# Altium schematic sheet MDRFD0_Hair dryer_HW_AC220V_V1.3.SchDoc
size A3; PageSetup: Record=PageOptions¦CenterHorizontal=True¦CenterVertical=True¦PrintScale=0.73¦XCorrection=1.00¦YCorrection=1.00¦PrintKind=0¦BorderSize=5000000¦LeftOffset=0¦BottomOffset=0¦Orientation=2¦PaperLength=1000¦PaperWidth=1000¦Scale=100¦PaperSource=7¦PrintQuality=-3¦MediaType=1¦DitherType=10¦PrintScaleMode=1¦PaperKind=A4¦PaperIndex=9
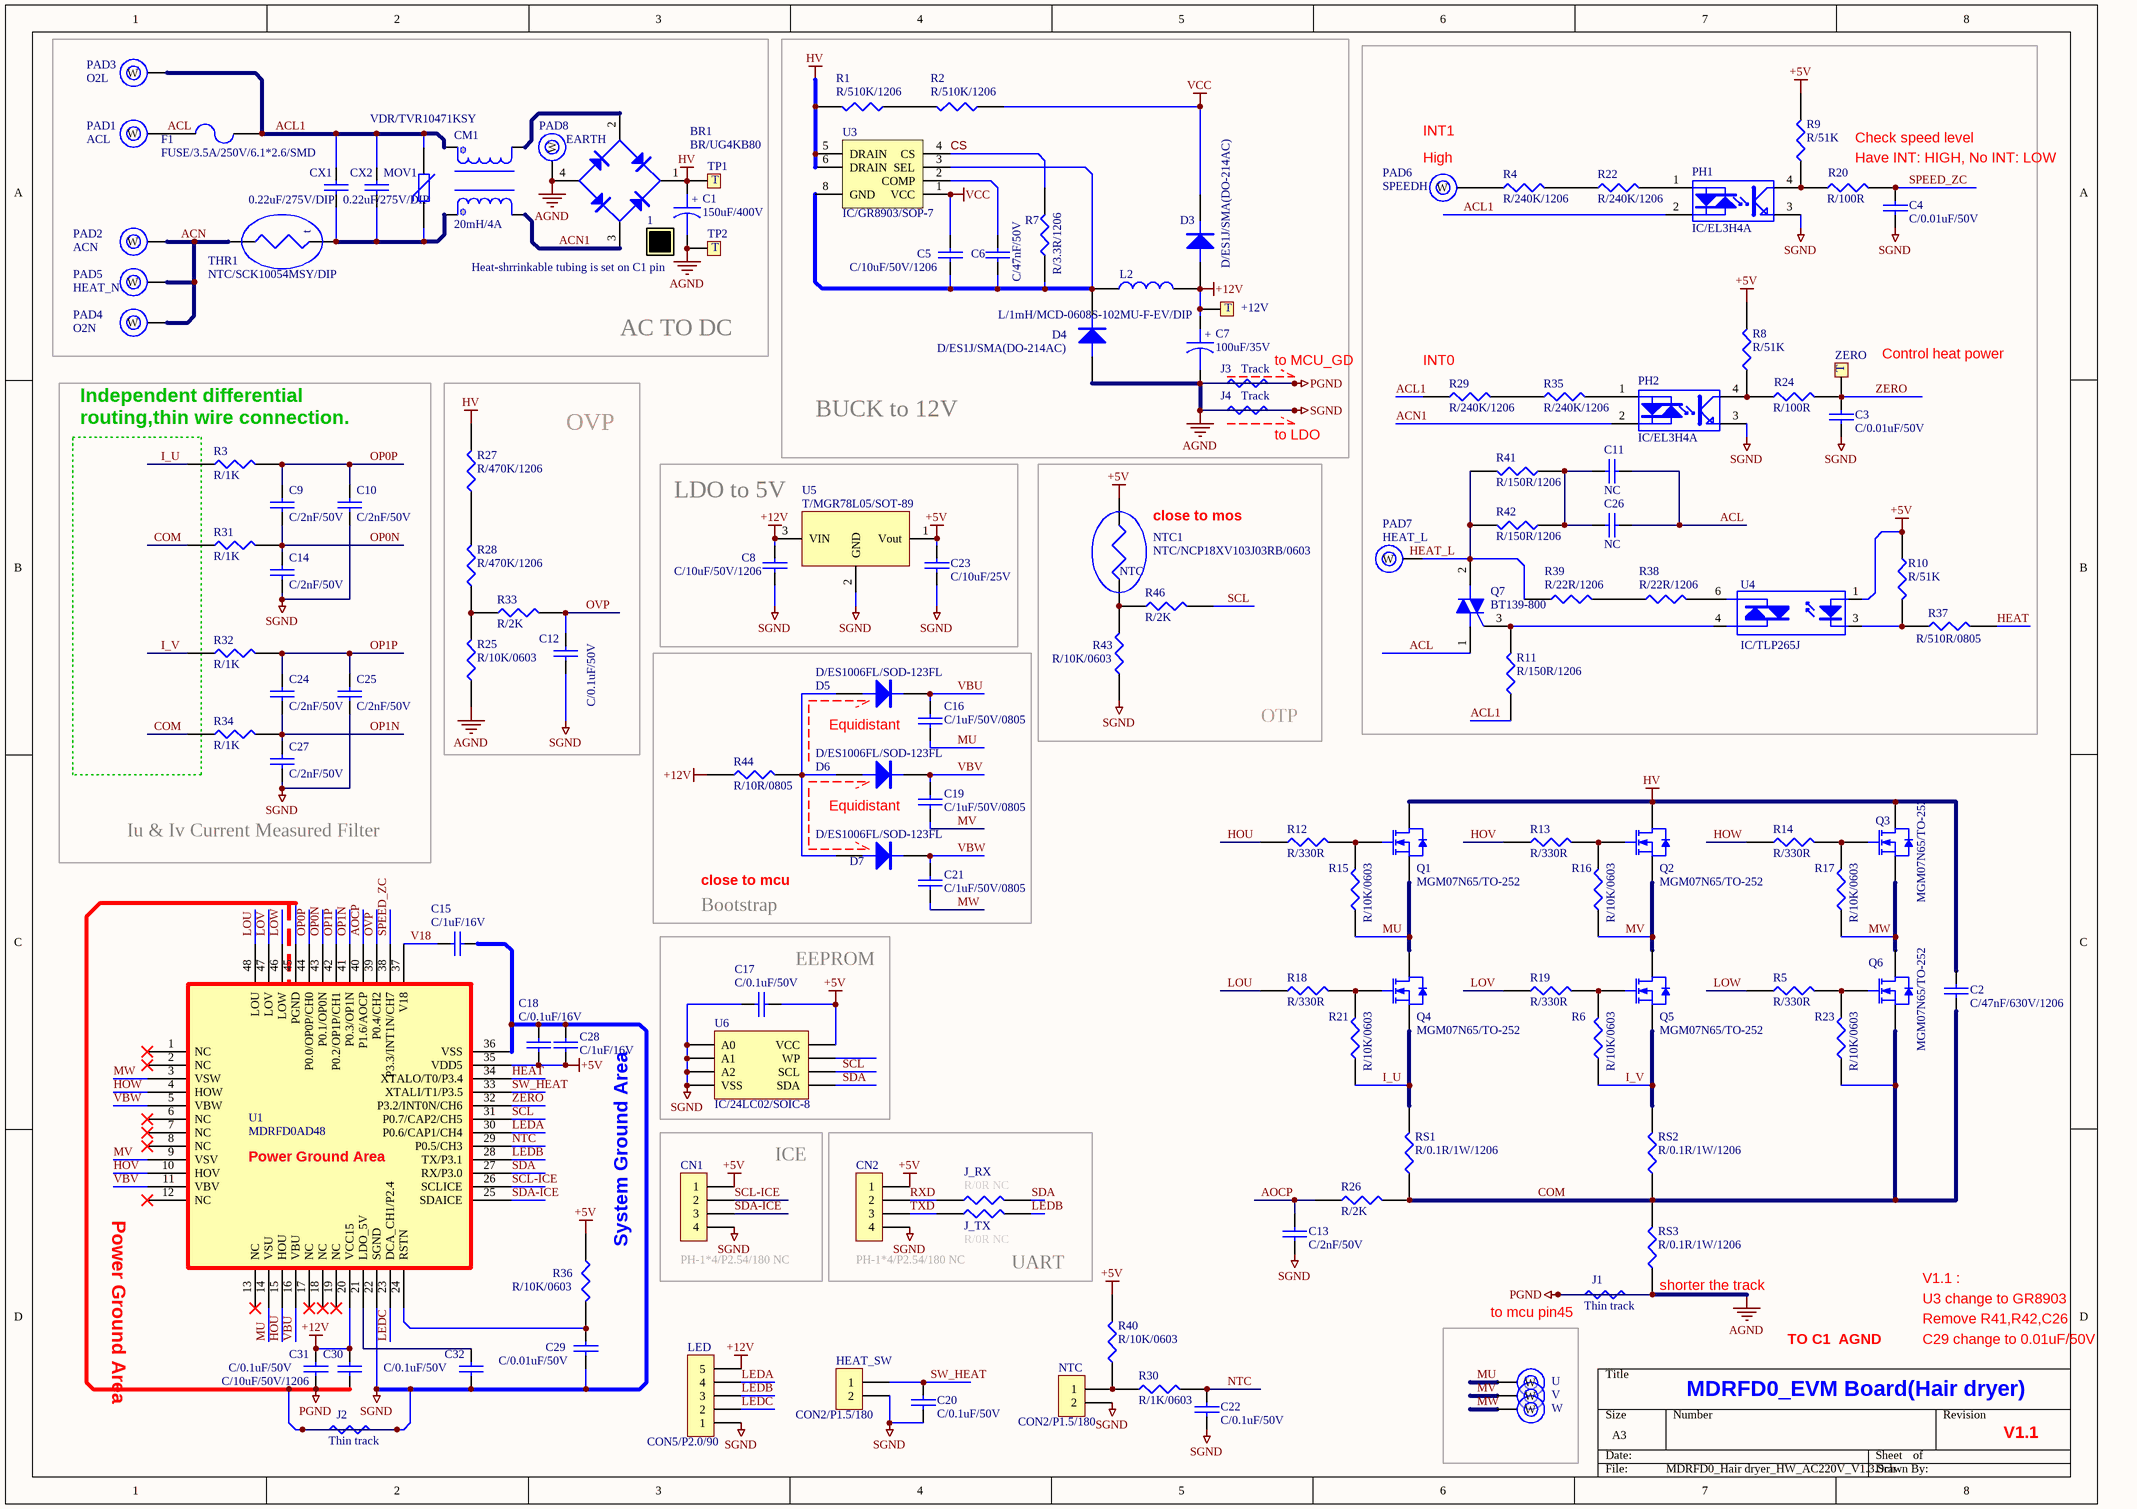
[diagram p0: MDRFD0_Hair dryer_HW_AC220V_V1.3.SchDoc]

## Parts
1  Heat-shrrinkable tubing is set on C1 pin
+12V  15V  [1MM]  (value not drawn)
BR1  BR/UG4KB80  [DB KBP410]
C1  150uF/400V  [33U400V]
C2  C/47nF/630V/1206  [C1206]
C3  C/0.01uF/50V  [C0603]
C4  C/0.01uF/50V  [C0603]
C5  C/10uF/50V/1206  [C1206]
C6  C/47nF/50V  [C0603]
C7  100uF/35V  [CAPACITOR 8*13]
C8  C/10uF/50V/1206  [C1206]
C9  C/2nF/50V  [C0603]
C10  C/2nF/50V  [C0603]
C11  NC  [C1206]
C12  C/0.1uF/50V  [C0603]
C13  C/2nF/50V  [C0603]
C14  C/2nF/50V  [C0603]
C15  C/1uF/16V  [C0603]
C16  C/1uF/50V/0805  [C0805]
C17  C/0.1uF/50V  [C0603]
C18  C/0.1uF/16V  [C0603]
C19  C/1uF/50V/0805  [C0805]
C20  C/0.1uF/50V  [C0603]
C21  C/1uF/50V/0805  [C0805]
C22  C/0.1uF/50V  [C0603]
C23  C/10uF/25V  [C0603]
C24  C/2nF/50V  [C0603]
C25  C/2nF/50V  [C0603]
C26  NC  [C1206]
C27  C/2nF/50V  [C0603]
C28  C/1uF/16V  [C0603]
C29  C/0.01uF/50V  [C0603]
C30  C/10uF/50V/1206  [C1206]
C31  C/0.1uF/50V  [C0603]
C32  C/0.1uF/50V  [C0603]
CM1  20mH/4A  [20mH]
CN1  PH-1*4/P2.54/180 NC  [SIP4]
CN2  PH-1*4/P2.54/180 NC  [SIP4]
CX1  0.22uF/275V/DIP  [CX 0.1UF]
CX2  0.22uF/275V/DIP  [CX 0.1UF]
D3  D/ES1J/SMA(DO-214AC)  [DIODE SMA]
D4  D/ES1J/SMA(DO-214AC)  [DIODE SMA]
D5  D/ES1006FL/SOD-123FL  [SOD-123FL]
D6  D/ES1006FL/SOD-123FL  [SOD-123FL]
D7  D/ES1006FL/SOD-123FL  [SOD-123FL]
F1  FUSE/3.5A/250V/6.1*2.6/SMD  [FUSE - 3.15A]
HEAT_SW  CON2/P1.5/180  [CN2P]
J1  Thin track
J2  Thin track
J3  Track
J4  Track
J_RX  R/0R NC  [R0603]
J_TX  R/0R NC  [R0603]
L2  L/1mH/MCD-0608S-102MU-F-EV/DIP  [L6*8]
LED  CON5/P2.0/90  [CN5P  2.0MM]
MOV1  VDR/TVR10471KSY  [MOV 10D471K]
NTC  CON2/P1.5/180  [CN2P]
NTC1  NTC/NCP18XV103J03RB/0603  [R0603]
PAD1  ACL  [1.5MM]
PAD2  ACN  [1.5MM]
PAD3  O2L  [1.5MM]
PAD4  O2N  [1.5MM]
PAD5  HEAT_N  [1.5MM]
PAD6  SPEEDH  [1.5MM]
PAD7  HEAT_L  [1.5MM]
PAD8  EARTH  [1.5MM]
PH1  IC/EL3H4A  [SOP4(1.27MM)]
PH2  IC/EL3H4A  [SOP4(1.27MM)]
Q1  MGM07N65/TO-252  [TO-252]
Q2  MGM07N65/TO-252  [TO-252]
Q3  MGM07N65/TO-252  [TO-252]
Q4  MGM07N65/TO-252  [TO-252]
Q5  MGM07N65/TO-252  [TO-252]
Q6  MGM07N65/TO-252  [TO-252]
Q7  BT139-800  [MOS-LS]
R1  R/510K/1206  [1206R]
R2  R/510K/1206  [1206R]
R3  R/1K  [R0603]
R4  R/240K/1206  [1206R]
R5  R/330R  [R0603]
R6  R/10K/0603  [R0603]
R7  R/3.3R/1206  [1206R]
R8  R/51K  [R0603]
R9  R/51K  [R0603]
R10  R/51K  [R0603]
R11  R/150R/1206  [1206R]
R12  R/330R  [R0603]
R13  R/330R  [R0603]
R14  R/330R  [R0603]
R15  R/10K/0603  [R0603]
R16  R/10K/0603  [R0603]
R17  R/10K/0603  [R0603]
R18  R/330R  [R0603]
R19  R/330R  [R0603]
R20  R/100R  [R0603]
R21  R/10K/0603  [R0603]
R22  R/240K/1206  [1206R]
R23  R/10K/0603  [R0603]
R24  R/100R  [R0603]
R25  R/10K/0603  [R0603]
R26  R/2K  [R0603]
R27  R/470K/1206  [1206R]
R28  R/470K/1206  [1206R]
R29  R/240K/1206  [1206R]
R30  R/1K/0603  [R0603]
R31  R/1K  [R0603]
R32  R/1K  [R0603]
R33  R/2K  [R0603]
R34  R/1K  [R0603]
R35  R/240K/1206  [1206R]
R36  R/10K/0603  [R0603]
R37  R/510R/0805  [R0805]
R38  R/22R/1206  [1206R]
R39  R/22R/1206  [1206R]
R40  R/10K/0603  [R0603]
R41  R/150R/1206  [1206R]
R42  R/150R/1206  [1206R]
R43  R/10K/0603  [R0603]
R44  R/10R/0805  [R0805]
R46  R/2K  [R0603]
RS1  R/0.1R/1W/1206  [R1206]
RS2  R/0.1R/1W/1206  [R1206]
RS3  R/0.1R/1W/1206  [R1206]
THR1  NTC/SCK10054MSY/DIP  [MOV 10D471K]
TP1  HV  [1MM]  (value not drawn)
TP2  AGND  [1MM]  (value not drawn)
U  U  [1.5MM]  (value not drawn)
U1  MDRFD0AD48  [LQFP-48]
U3  IC/GR8903/SOP-7  [SOP-7]
U4  IC/TLP265J  [SOP 4/TLP265J]
U5  T/MGR78L05/SOT-89  [SOT89-3]
U6  IC/24LC02/SOIC-8  [SOP 8]
V  V  [1.5MM]  (value not drawn)
W  W  [1.5MM]  (value not drawn)
ZERO  ZERO  [1MM]  (value not drawn)

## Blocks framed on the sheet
AC TO DC: 1 BR1 C1 CM1 CX1 CX2 F1 MOV1 PAD1-PAD5 PAD8 THR1 TP1 TP2
BUCK to 12V: +12V C5-C7 D3 D4 J3 J4 L2 R1 R2 R7 U3
Iu & Iv Current Measured Filter: C9 C10 C14 C24 C25 C27 R3 R31 R32 R34
OVP: C12 R25 R27 R28 R33
LDO to 5V: C8 C23 U5
OTP: NTC1 R43 R46
Bootstrap: C16 C19 C21 D5-D7 R44
Power Ground Area: U1
EEPROM: C17 U6
ICE: CN1
UART: CN2 J_RX J_TX
to mcu pin45: U V W

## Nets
+5V: C17.2 C18.1 C23.2 C28.1 CN1.1 CN2.1 NTC1.1 R8.2 R9.2 R10.2 R36.2 R40.2 U1.35(VDD5) U4.1(A) U5.1(Vout) U6.8(VCC)
+12V: +12V.1(T) C7.1 C8.1 C30.1 C31.1 D3.1(A) L2.2 LED.5 R44.1 U1.20(VCC15) U5.3(VIN)
AGND: BR1.4(V-) C1.2 C3.1 C4.1 C7.2 C8.2 C10.2 C12.1 C13.2 C14.2 C15.2 C17.1 C18.2 C20.2 C22.2 C23.1 C25.2 C27.2 C28.2 C29.1 C30.2 C31.2 C32.2 CN1.4 CN2.4 D4.1(A) HEAT_SW.2 J1.1 J1.2 J2.1 J2.2 J3.1 J3.2 J4.1 J4.2 LED.1 NTC.2 PAD8.1(W) PH1.3(E) PH2.3(E) R25.1 R43.1 RS3.1 TP2.1(T) U1.22(SGND) U1.36(VSS) U1.45(PGND) U5.2(GND) U6.1(A0) U6.2(A1) U6.3(A2) U6.4(VSS)  [also labelled PGND, SGND]
HV: BR1.1(V+) C1.1 C2.1 Q1.2(D) Q2.2(D) Q3.2(D) R1.2 R27.2 TP1.1(T) U3.5(DRAIN) U3.6(DRAIN)
VCC: C5.1 D3.2(K) R2.1 U3.1(VCC)
ACL: C11.2 C26.2 F1.1 PAD1.1(W) Q7.1(T1)
ACL1: CM1.4 CX1.1 CX2.1 F1.2 MOV1.1 PAD3.1(W) PH1.2(K) R11.1 R29.1
ACN: PAD2.1(W) PAD4.1(W) PAD5.1(W) THR1.1
ACN1: BR1.3(AC) CM1.2 PH2.2(K)
AOCP: C13.1 R26.1 U1.40(P1.6/AOCP)
COM: C2.2 Q6.3(S) R23.1 R26.2 R31.1 R34.1 RS1.1 RS2.1 RS3.2
CS: R7.2 U3.4(CS)
HEAT: R37.2 U1.34(XTALO/T0/P3.4)
HOU: R12.1 U1.15(HOU)
HOV: R13.1 U1.10(HOV)
HOW: R14.1 U1.4(HOW)
I_U: Q4.3(S) R3.1 R21.1 RS1.2
I_V: Q5.3(S) R6.1 R32.1 RS2.2
LEDA: LED.4 U1.30(P0.6/CAP1/CH4)
LEDB: J_TX.2 LED.3 U1.28(TX/P3.1)
LEDC: LED.2 U1.23(DCA_CH1/P2.4)
LOU: R18.1 U1.48(LOU)
LOV: R19.1 U1.47(LOV)
LOW: R5.1 U1.46(LOW)
MU: C16.2 Q1.3(S) Q4.2(D) R15.1 U.1(W) U1.14(VSU)
MV: C19.2 Q2.3(S) Q5.2(D) R16.1 U1.9(VSV) V.1(W)
MW: C21.2 Q3.3(S) Q6.2(D) R17.1 U1.3(VSW) W.1(W)
NTC: C22.1 R30.2 U1.29(P0.5/CH3)
OP0N: C9.2 C14.1 R31.2 U1.43(P0.1/OP0N)
OP0P: C9.1 C10.1 R3.2 U1.44(P0.0/OP0P/CH0)
OP1N: C24.2 C27.1 R34.2 U1.41(P0.3/OP1N)
OP1P: C24.1 C25.1 R32.2 U1.42(P0.2/OP1P/CH1)
OVP: C12.2 R33.2 U1.39(P0.4/CH2)
RXD: CN2.2 J_RX.1
SCL: R46.2 U1.31(P0.7/CAP2/CH5) U6.6(SCL)
SCL-ICE: CN1.2 U1.26(SCLICE)
SDA: J_RX.2 U1.27(RX/P3.0) U6.5(SDA)
SDA-ICE: CN1.3 U1.25(SDAICE)
SPEED_ZC: C4.2 R20.2 U1.38(P3.3/INT1N/CH7)
SW_HEAT: C20.1 HEAT_SW.1 U1.33(XTALI/T1/P3.5)
TXD: CN2.3 J_TX.1
V18: C15.1 U1.37(V18)
VBU: C16.1 D5.2(K) U1.16(VBU)
VBV: C19.1 D6.2(K) U1.11(VBV)
VBW: C21.1 D7.2(K) U1.5(VBW)
ZERO: C3.2 R24.2 U1.32(P3.2/INT0N/CH6) ZERO.1(T)
NetBR1_2: BR1.2(AC) CM1.3
NetC5_2: C5.2 C6.1 D4.2(K) L2.1 R7.1 U3.3(SEL) U3.8(GND)
NetC6_2: C6.2 U3.2(COMP)
NetC11_1: C11.1 C26.1 R41.1 R42.1
NetC29_2: C29.2 R36.1 U1.24(RSTN)
NetC32_1: C32.1 U1.21(LDO_5V)
NetCM1_1: CM1.1 CX1.2 CX2.2 MOV1.2 THR1.2
NetD5_1: D5.1(A) D6.1(A) D7.1(A) R44.2
NetNTC1_2: NTC1.2 R43.2 R46.1
NetNTC_1: NTC.1 R30.1 R40.1
NetPAD6_1: PAD6.1(W) R4.1
NetPAD7_1: PAD7.1(W) Q7.2(T2) R39.1 R41.2 R42.2
NetPH1_1: PH1.1(A) R22.2
NetPH1_4: PH1.4(C) R9.1 R20.1
NetPH2_1: PH2.1(A) R35.2
NetPH2_4: PH2.4(C) R8.1 R24.1
NetQ1_1: Q1.1(G) R12.2 R15.2
NetQ2_1: Q2.1(G) R13.2 R16.2
NetQ3_1: Q3.1(G) R14.2 R17.2
NetQ4_1: Q4.1(G) R18.2 R21.2
NetQ5_1: Q5.1(G) R6.2 R19.2
NetQ6_1: Q6.1(G) R5.2 R23.2
NetQ7_3: Q7.3(G) R11.2 U4.4(A/K)
NetR1_1: R1.1 R2.2
NetR4_2: R4.2 R22.1
NetR10_1: R10.1 R37.1 U4.3(K)
NetR25_2: R25.2 R28.1 R33.1
NetR27_1: R27.1 R28.2
NetR29_2: R29.2 R35.1
NetR38_1: R38.1 R39.2
NetR38_2: R38.2 U4.6(A/K)

Not connected (* = marked no-connect by the designer): U1 1(NC)* 2(NC)* 6(NC)* 7(NC)* 8(NC)* 12(NC)* 13(NC)* 17(NC)* 18(NC)* 19(NC)*; U6 7(WP)

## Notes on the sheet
- (near PAD6) High
- INT1
- Check speed level
- Have INT: HIGH, No INT: LOW
- (near J3) to MCU_GD
- (near R29) INT0
- Control heat power
- (near R3) Independent differential routing,thin wire connection.
- (near J4) to LDO
- (near NTC1) close to mos
- Equidistant
- close to mcu
- Power Ground Area
- (near R36) System Ground Area
- (near RS3) shorter the track
- V1.1 :
- U3 change to GR8903
- Remove R41,R42,C26
- MDRFD0_EVM Board(Hair dryer)
- TO C1  AGND
- C29 change to 0.01uF/50V
- V1.1
- Labels drawn without touching a wire or pin: HEAT_L

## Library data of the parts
1 = Note
+12V TP1 TP2 ZERO = TESTPOINT
BR1 = BR/UG4KB80: UG4KB80,4A,800V,10.8*13.8mm(L*W),GULFSEMI, DIP,凱恩傑
C1 = C/E/150uF/400V/18*40: N.C.C,KXJ,150uF,400V,±20%,P:7.5*18*40,DIP,105℃
C2 = C/47nF/630V/1206: TDK,47nF,630V,±10%,1206; SMD/DIP/WELDING: SMD
C3 C4 C29 = C/0.01uF/50V: PSA,0603B103K500,0.01uF(103)(10n),50V,±10%,X7R,0603,SMD
C5 C8 C30 = C/10uF/50V/1206: PSA,1206X106K500CT,10uF,50V,±20%,X5R,1206,SMD
C6 C12 C17 C20 C22 C31 C32 = C/0.1uF/50V: 0.1uF(104)(100n),50V,±10%,X7R,0603,PSA; SMD/DIP/WELDING: SMD
C7 = C/E/100uF/35V/6.3*11: 100uF,35V,ψ6,6.3*11; SMD/DIP/WELDING: DIP
C9 C10 C14 C24 C25 C27 = C/2nF/16V: 2nF/50V/±15%/X7R,0603,PSA; SMD/DIP/WELDING: SMD
C11 C26 = C/0.22uF/100V/1206: SMD/DIP/WELDING: SMD
C13 = C/2nF/50V: 2nF/50V/±15%/X7R,0603,PSA; SMD/DIP/WELDING: SMD
C15 C28 = C/1uF/16V: 1uF(105),16V,±10%,X7R,0603,PSA,世愛; SMD/DIP/WELDING: SMD
C16 C19 C21 = C/1uF/50V/0805: 1uF(105)(1000n) ,  50V , -20+80% , X7R , 0805,世愛; SMD/DIP/WELDING: SMD
C18 = C/0.1uF/16V: 0.1uF(104)(100n),16V,±10%,X7R,0603,PSA; SMD/DIP/WELDING: SMD
C23 = C/10uF/25V: 晶片電容 10uF(106),25V,+/-10%,X5R,0603,世愛; SMD/DIP/WELDING: SMD
CM1 = GM
CN1 CN2 = PH-1*4/P2.54/180: CHERNG WEEI,P101-SGP-100/030-4,Pitch:2.54mm,4Pin,180度,L:10.16mm*W:2.54mm*H:10mm,Header,PBT; SMD/DIP/WELDING: DIP
CX1 CX2 = C/X/0.22uF/275V/DIP: 金屬化塑膠AC電容 PXK , 0.22uF(224) , 275V , Class X2 , AC/±10% , 18*9.5*15.5(L*T*H) , Pitch：15;MKP,0.22uF(224),275V,Class X2,AC/±10%,L:18mm*D:8mm*H:13mm,Pitch:15mm,HUA JUNG; SMD/DIP/WELDING: DIP
D3 D4 = D/ES1J/SMA(DO-214AC): PANJIT,ES1J ,600V,1A,DO-214AC,SMD
D5-D7 = D/ES1006FL/SOD-123FL: ES1006FL,SOD-123FL; SMD/DIP/WELDING: SMD
F1 = FUSE/3.15A/250V/4*8.5/DIP: 3.5A,250V,6.1mm*2.6mm(2410); SMD/DIP/WELDING: SMD
HEAT_SW NTC = CON2/P1.5/180: Header 180度,CP-W15-02,Pitch:1.5mm,2Pin,承洧; SMD/DIP/WELDING: DIP
J1 J2 = R/0.01R/1206: SMD/DIP/WELDING: SMD
J3 J4 = R/0.01R/1206: Thin track; SMD/DIP/WELDING: SMD
J_RX J_TX = R/0R: 晶片電阻  0R , 1% , 0603,世愛; SMD/DIP/WELDING: SMD
L2 = L/1mH/MCD-0608S-102MU-F-EV/DIP: MAG.LAYERS,MCD-0608S-102MU-F-EV,1mH,0.25A,ψ8mm*10mm,DIP
LED = CON5/P2.0/90: TKP,P110L-05,P:2.0,5Pin,90度,12*7.6*4.6,DIP
MOV1 = VDR/TVR10471KSY: TKS,TVR10471KSY,470V,±10%,ψ10mm,D:12.5mm,Pitch:7.5mm,DIP
NTC1 = NTC/NCP18XV103J03RB/0603: Murata,NCP18XV103J03RB,10KΩ,β:3900,0.31mA(25°C),100mW,SMD,0603,-40°C~+125°C
PAD1-PAD8 U V W = PAD/WELDING: WELDING; ComponentlLink1URL: Y:\T130-設計三部\Datasheet\SW\XL04-10-16-8中?(TOUCH).pdf
PH1 PH2 = IC/EL3H4A: EVERLIGHT,EL3H4A,4Pin,SMD,AC Input Photocoupler,1mA(IF),5V(VCE)
Q1-Q6 = T/EM07N65/TO-252: EnergicTek,EM07N65,650V,7A,1.4Ω,TO-252,SMD,N-Channel Fast Switching MOSFET
Q7 = Triac: Silicon Bidirectional Triode Thyristor; Note: Pin 2 is electrically connected to Pin 4 (TAB)
R1 R2 = R/510K/1206: 510K/1206; SMD/DIP/WELDING: SMD
R3 R31 R32 R34 = R/1K: 1K,1%,0603,PSA; SMD/DIP/WELDING: SMD
R4 R22 R29 R35 = R/240K/1206: 240K,5%,1206; SMD/DIP/WELDING: SMD
R5 R12-R14 R18 R19 = R/330R: 330R,1%,0603，世愛; SMD/DIP/WELDING: SMD
R6 R15-R17 R21 R23 R25 R36 R40 R43 = R/10K/0603: PSA,WR06X1002FTL,10KΩ,0603,SMD
R7 = R/3.3R/1206: 3.3R,1%,1206,PSA; SMD/DIP/WELDING: SMD
R8-R10 = R/51K: 51K,1%,0603,PSA; SMD/DIP/WELDING: SMD
R11 R41 R42 RS1-RS3 = R/150R/1206: 150R,1%,1206,PSA; SMD/DIP/WELDING: SMD
R20 R24 = R/100R: 100R,1%,0603,PSA,世愛; SMD/DIP/WELDING: SMD
R26 R33 = R/2K: 2K,5%,0603,PSA,世愛; SMD/DIP/WELDING: SMD
R27 R28 = R/470K/1206: 470K,1%,1206,PSA; SMD/DIP/WELDING: SMD
R30 = R/1K/0603: 1K,1%,0603,PSA; SMD/DIP/WELDING: SMD
R37 = R/510R/0805: 510R,1%,0805,PSA; SMD/DIP/WELDING: SMD
R38 R39 = R/22R/1206: 22R,1%,1206,PSA(世愛); SMD/DIP/WELDING: SMD
R44 = R/10R/0805: PSA,WR08X10R0FTL,10R,0805,SMD
R46 = R/2K: 2K,1%,0603,PSA,世愛; SMD/DIP/WELDING: SMD
THR1 = NTC/SCK10054MSY/DIP: THINKING,SCK10054MSY,5R,4A,ψ10mm,P:5mm,DIP
U1 = MDRFD0-LQFP48
U3 = IC/GR8903/SOP-7: Grenergy,GR8903AKAG,SOP-7,SMD,Vo=15V,Iomax=0.25A
U4 = IC/TLP265J: TOSHIBA,TLP265J,4Pin,SMD,Photocouplers,10mA(IF),600V
U5 = T/APL78L05/SOT-89: MGR78L05
U6 = IC/24LC02/SOIC-8: MicroChip,24LC02BT-I/SN,2K,8PIN,I2C/SOIC-8,EEPROM,SMD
